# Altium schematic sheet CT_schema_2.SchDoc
size 379 x 228 mm
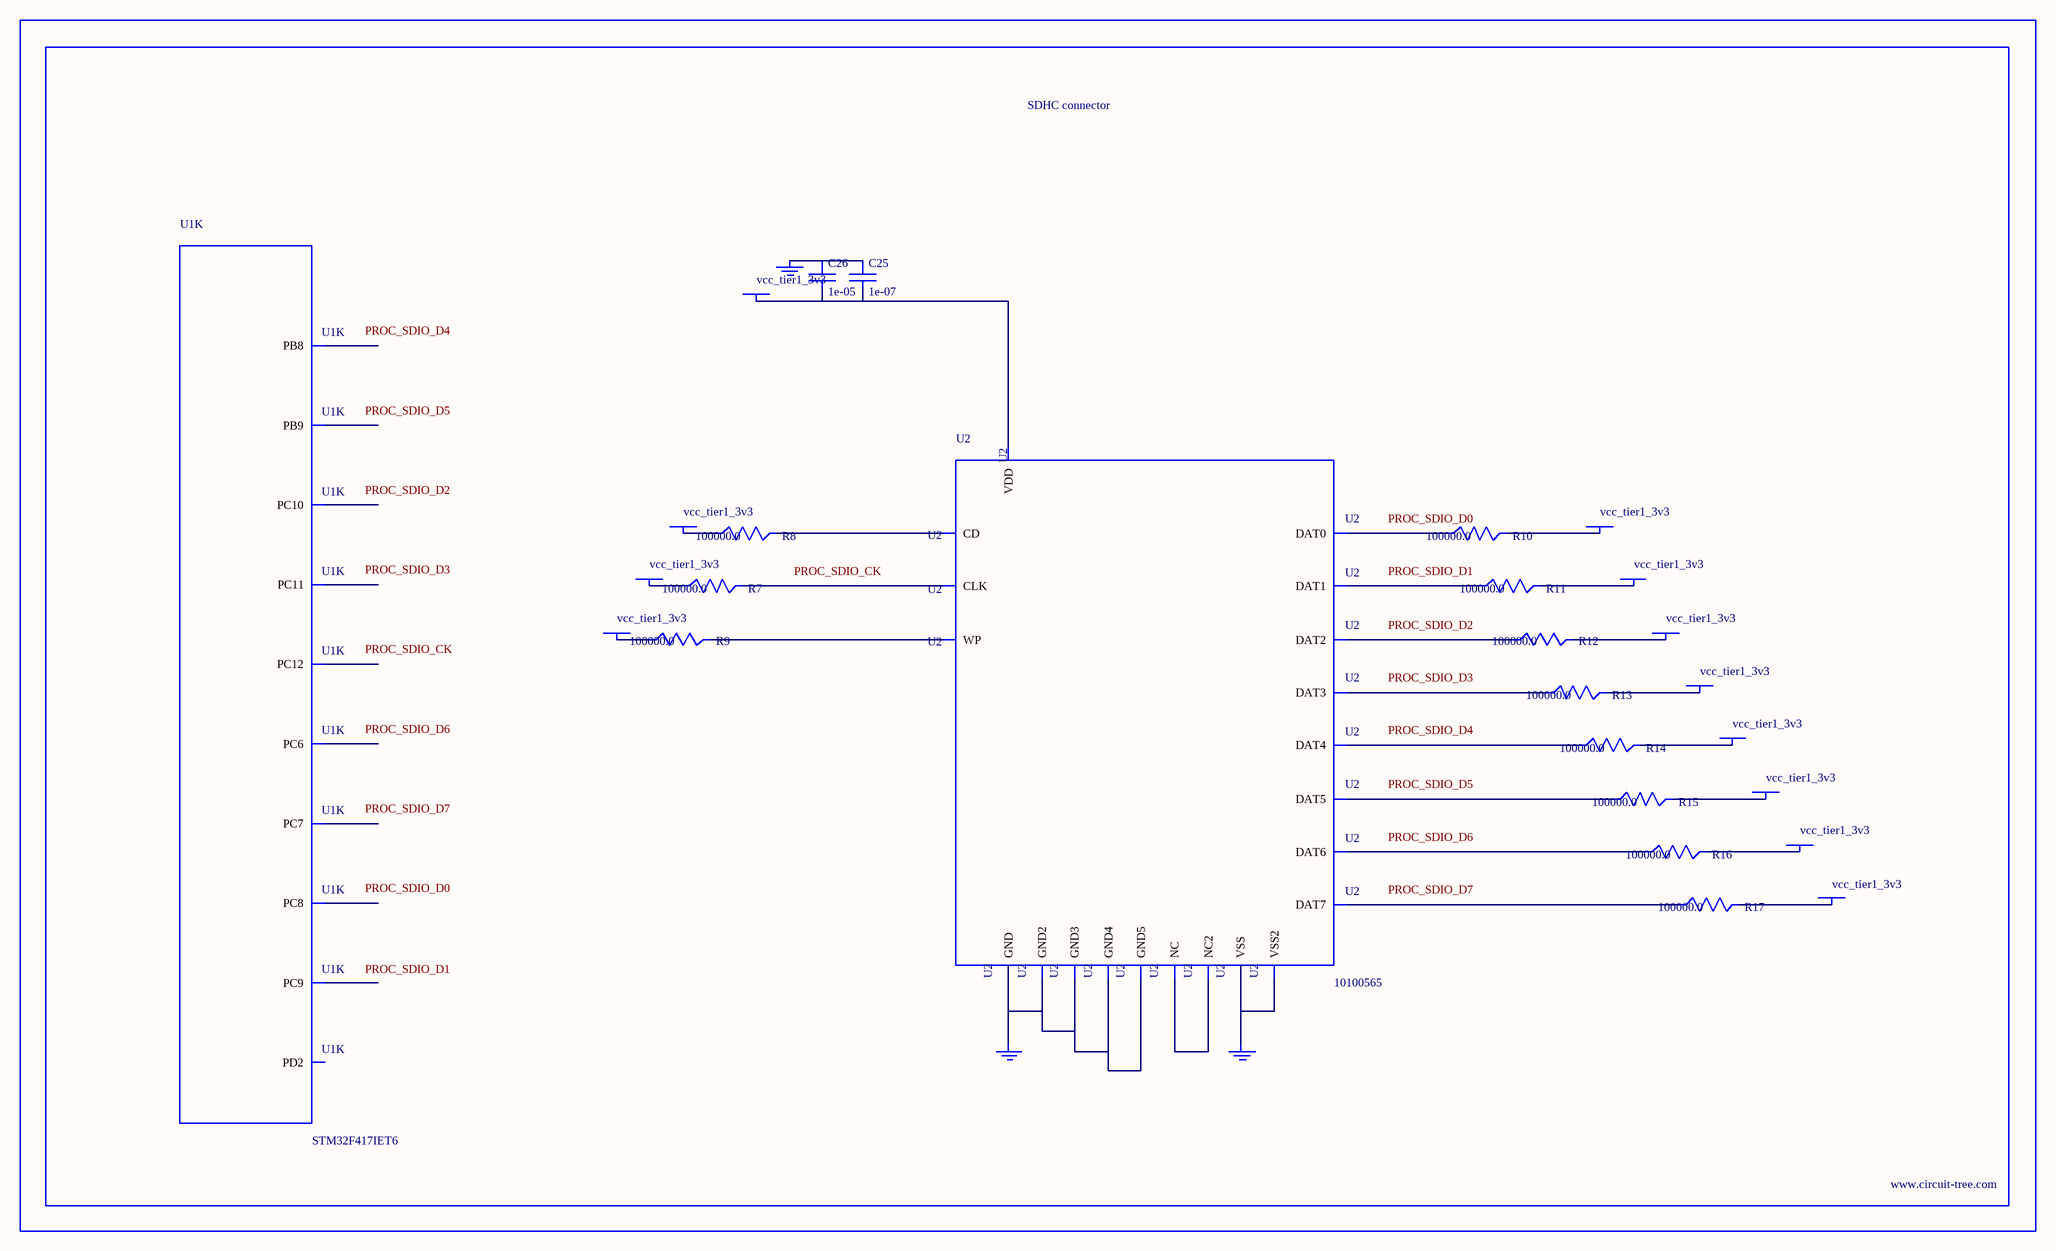
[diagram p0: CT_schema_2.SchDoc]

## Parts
BORDER1  (no value)
C25  1e-07  [C0402]
C26  1e-05  [C0805]
GND_INSTANCE_1_0  (no value)
GND_INSTANCE_1_1  (no value)
GND_INSTANCE_1_2  (no value)
POWER_INSTANCE_1_0  vcc_tier1_3v3
POWER_INSTANCE_1_1  vcc_tier1_3v3
POWER_INSTANCE_1_2  vcc_tier1_3v3
POWER_INSTANCE_1_3  vcc_tier1_3v3
POWER_INSTANCE_1_4  vcc_tier1_3v3
POWER_INSTANCE_1_5  vcc_tier1_3v3
POWER_INSTANCE_1_6  vcc_tier1_3v3
POWER_INSTANCE_1_7  vcc_tier1_3v3
POWER_INSTANCE_1_8  vcc_tier1_3v3
POWER_INSTANCE_1_9  vcc_tier1_3v3
POWER_INSTANCE_1_10  vcc_tier1_3v3
POWER_INSTANCE_1_11  vcc_tier1_3v3
R7  100000.0  [R0603]
R8  100000.0  [R0603]
R9  100000.0  [R0603]
R10  100000.0  [R0603]
R11  100000.0  [R0603]
R12  100000.0  [R0603]
R13  100000.0  [R0603]
R14  100000.0  [R0603]
R15  100000.0  [R0603]
R16  100000.0  [R0603]
R17  100000.0  [R0603]
U1  STM32F417IET6  [LQFP176]  (part K of 14)
U2  10100565  [10100565]

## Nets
NetC25_1: C25.1 C26.1 GND_INSTANCE_1_0.0(GND)
NetC25_2: C25.2 C26.2 POWER_INSTANCE_1_7.0(PWR) U2.9(VDD)
NetGND_INSTANCE_1_1_0: GND_INSTANCE_1_1.0(GND) U2.6(VSS) U2.10(VSS2)
NetGND_INSTANCE_1_2_0: GND_INSTANCE_1_2.0(GND) U2.12(GND) U2.16(GND2) U2.17(GND3) U2.20(GND4) U2.21(GND5)
NetPOWER_INSTANCE_1_0_0: POWER_INSTANCE_1_0.0(PWR) R9.1
NetPOWER_INSTANCE_1_1_0: POWER_INSTANCE_1_1.0(PWR) R8.1
NetPOWER_INSTANCE_1_2_0: POWER_INSTANCE_1_2.0(PWR) R11.2
NetPOWER_INSTANCE_1_3_0: POWER_INSTANCE_1_3.0(PWR) R10.2
NetPOWER_INSTANCE_1_4_0: POWER_INSTANCE_1_4.0(PWR) R17.2
NetPOWER_INSTANCE_1_5_0: POWER_INSTANCE_1_5.0(PWR) R16.2
NetPOWER_INSTANCE_1_6_0: POWER_INSTANCE_1_6.0(PWR) R7.1
NetPOWER_INSTANCE_1_8_0: POWER_INSTANCE_1_8.0(PWR) R15.2
NetPOWER_INSTANCE_1_9_0: POWER_INSTANCE_1_9.0(PWR) R14.2
NetPOWER_INSTANCE_1_10_0: POWER_INSTANCE_1_10.0(PWR) R13.2
NetPOWER_INSTANCE_1_11_0: POWER_INSTANCE_1_11.0(PWR) R12.2
NetR7_2: R7.2 U2.8(CLK)
NetR8_2: R8.2 U2.2(CD)
NetR9_2: R9.2 U2.1(WP)
NetR10_1: R10.1 U2.4(DAT0)
NetR11_1: R11.1 U2.3(DAT1)
NetR12_1: R12.1 U2.15(DAT2)
NetR13_1: R13.1 U2.14(DAT3)
NetR14_1: R14.1 U2.13(DAT4)
NetR15_1: R15.1 U2.11(DAT5)
NetR16_1: R16.1 U2.7(DAT6)
NetR17_1: R17.1 U2.5(DAT7)
NetU2_18: U2.18(NC) U2.19(NC2)

Not connected (* = marked no-connect by the designer): U1 115(PC6) 116(PC7) 117(PC8) 118(PC9) 139(PC10) 140(PC11) 141(PC12) 144(PD2) 167(PB8) 168(PB9)

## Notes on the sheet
- Labels drawn without touching a wire or pin: PROC_SDIO_CK, PROC_SDIO_D0, PROC_SDIO_D1, PROC_SDIO_D2, PROC_SDIO_D3, PROC_SDIO_D4, PROC_SDIO_D5, PROC_SDIO_D6, PROC_SDIO_D7

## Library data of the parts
BORDER1 = BORDER_PAGE1
C25 = C0402C104K3RACTU
C26 = C0805C106K8RACTU
GND_INSTANCE_1_0-GND_INSTANCE_1_2 = GND
POWER_INSTANCE_1_0-POWER_INSTANCE_1_11 = PWR
R7-R17 = RC0603JR-07100KL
